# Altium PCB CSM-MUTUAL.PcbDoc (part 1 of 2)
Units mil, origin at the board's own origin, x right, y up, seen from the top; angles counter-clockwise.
Board outline 5500 x 4000 mil, 2 copper layers (Top Layer, Bottom Layer), stack 62 mil thick; 159 components, 115 nets, 998 pads, 195 vias.
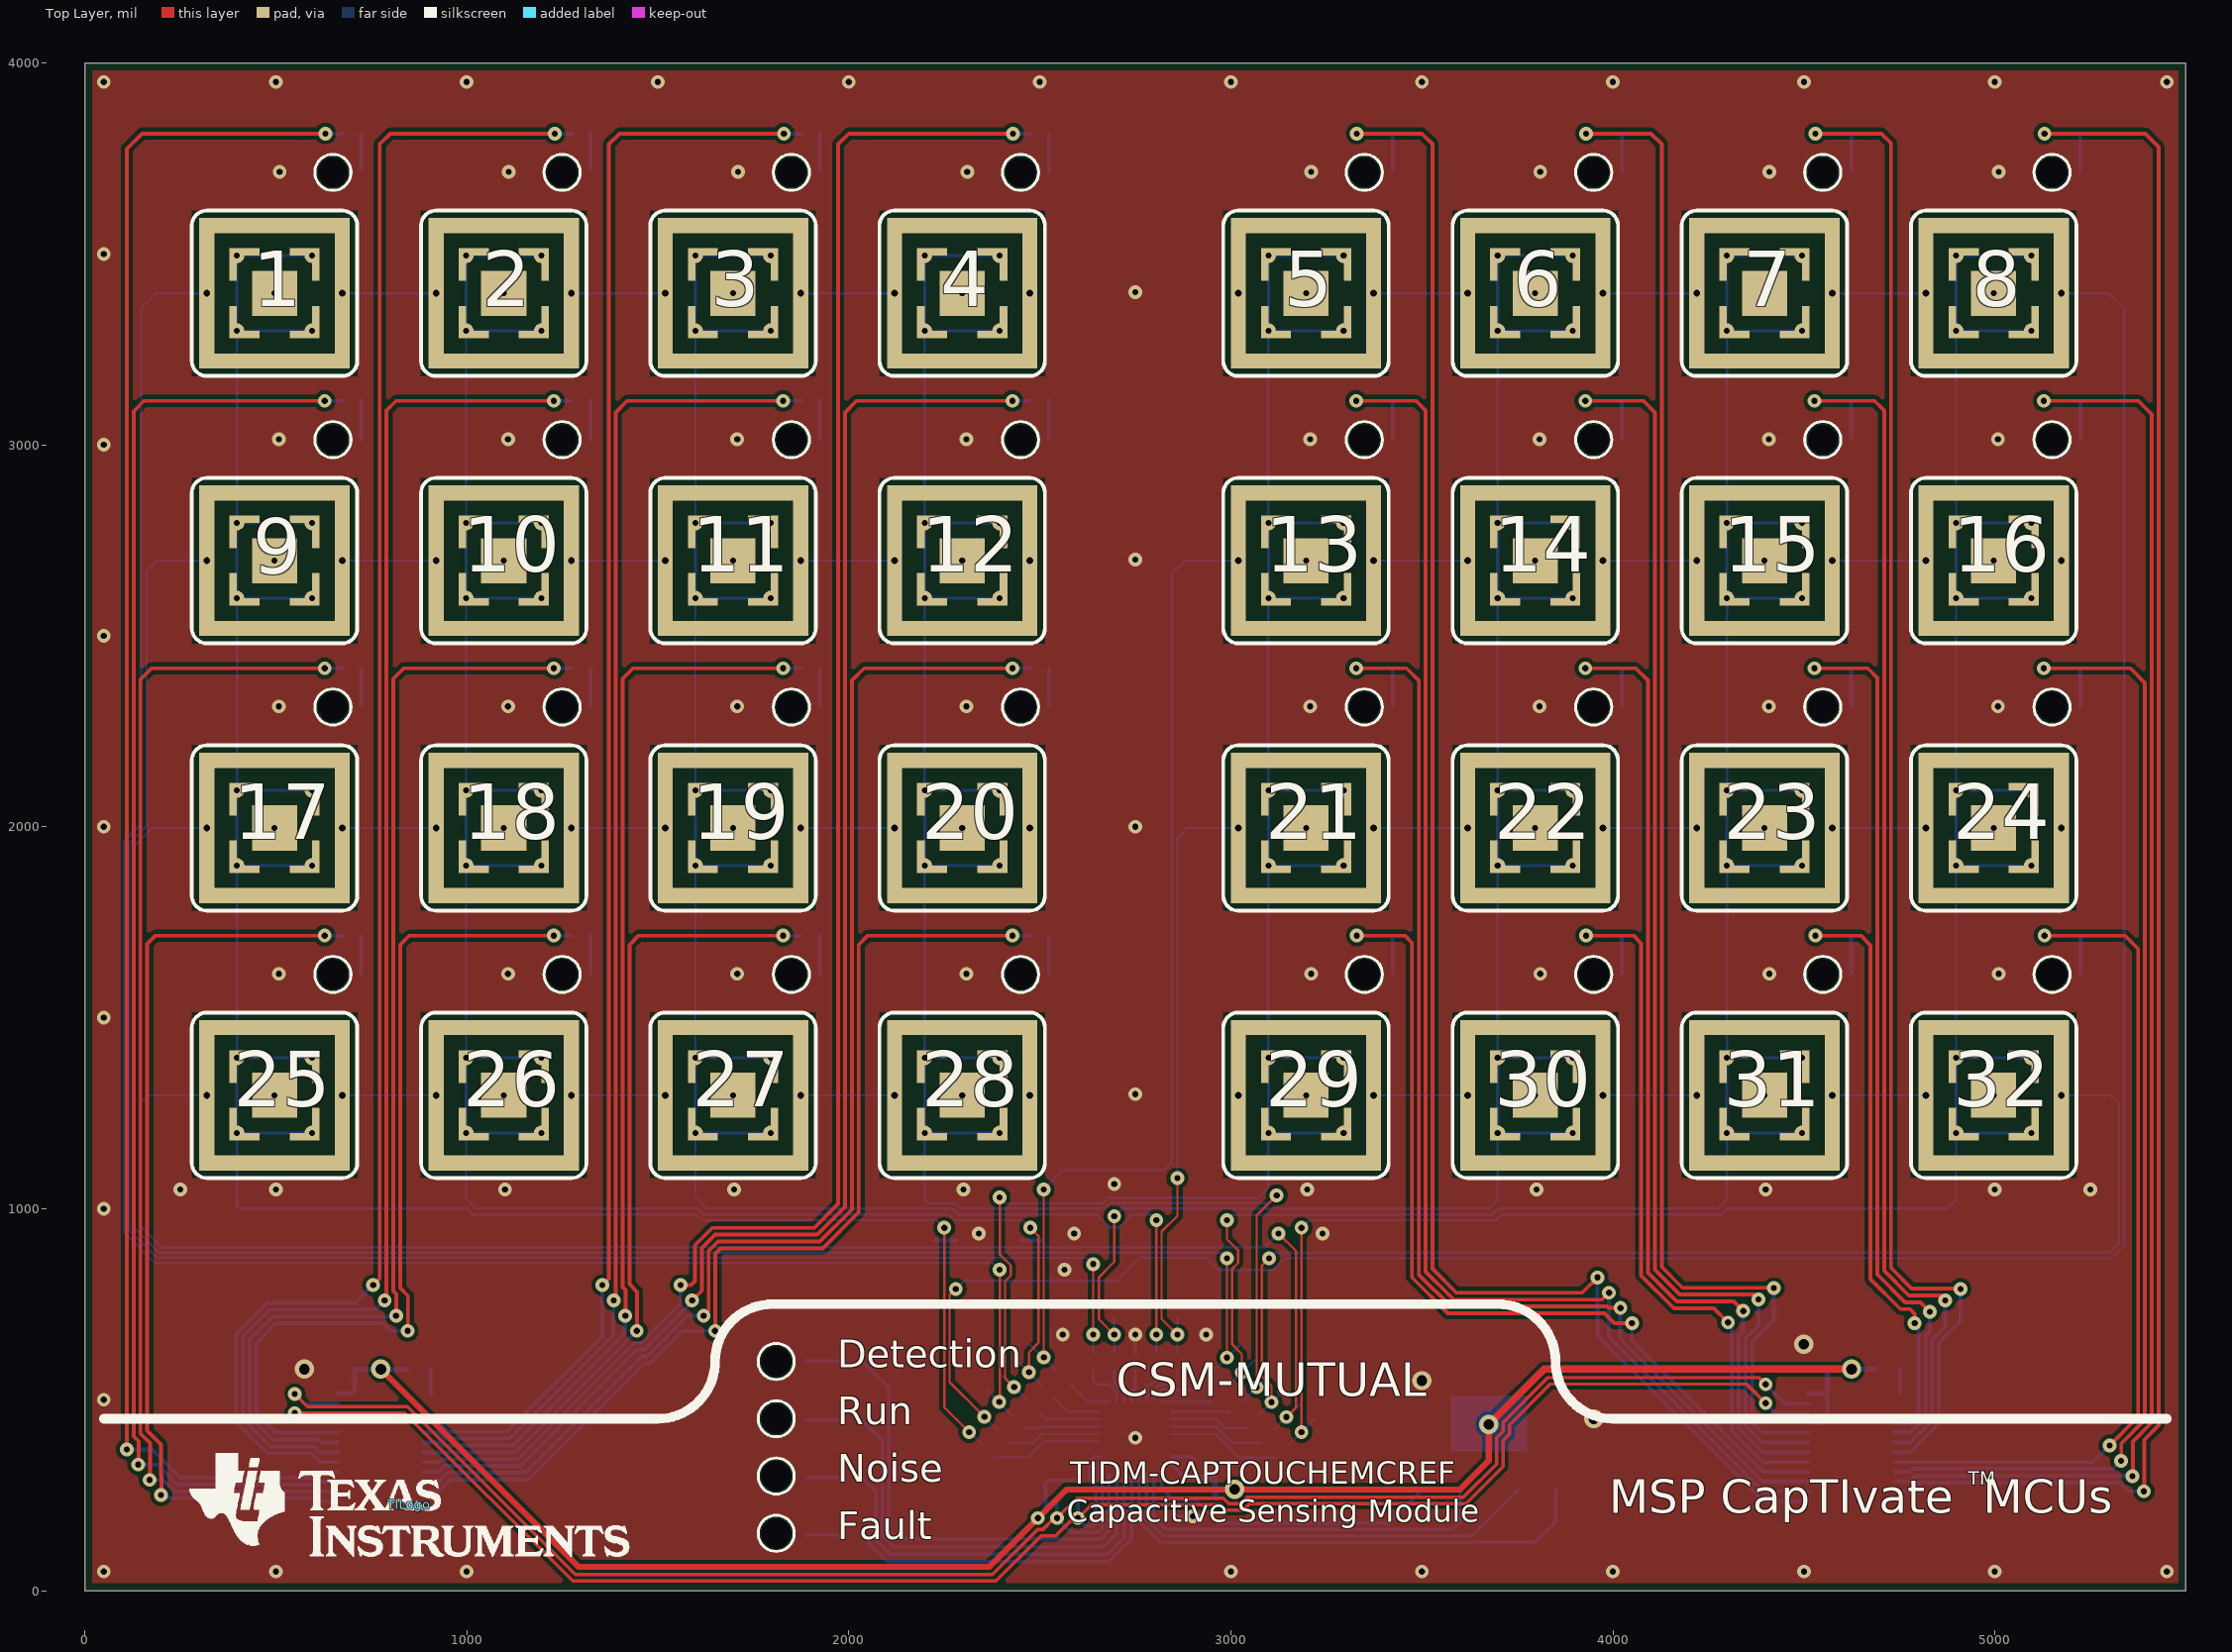
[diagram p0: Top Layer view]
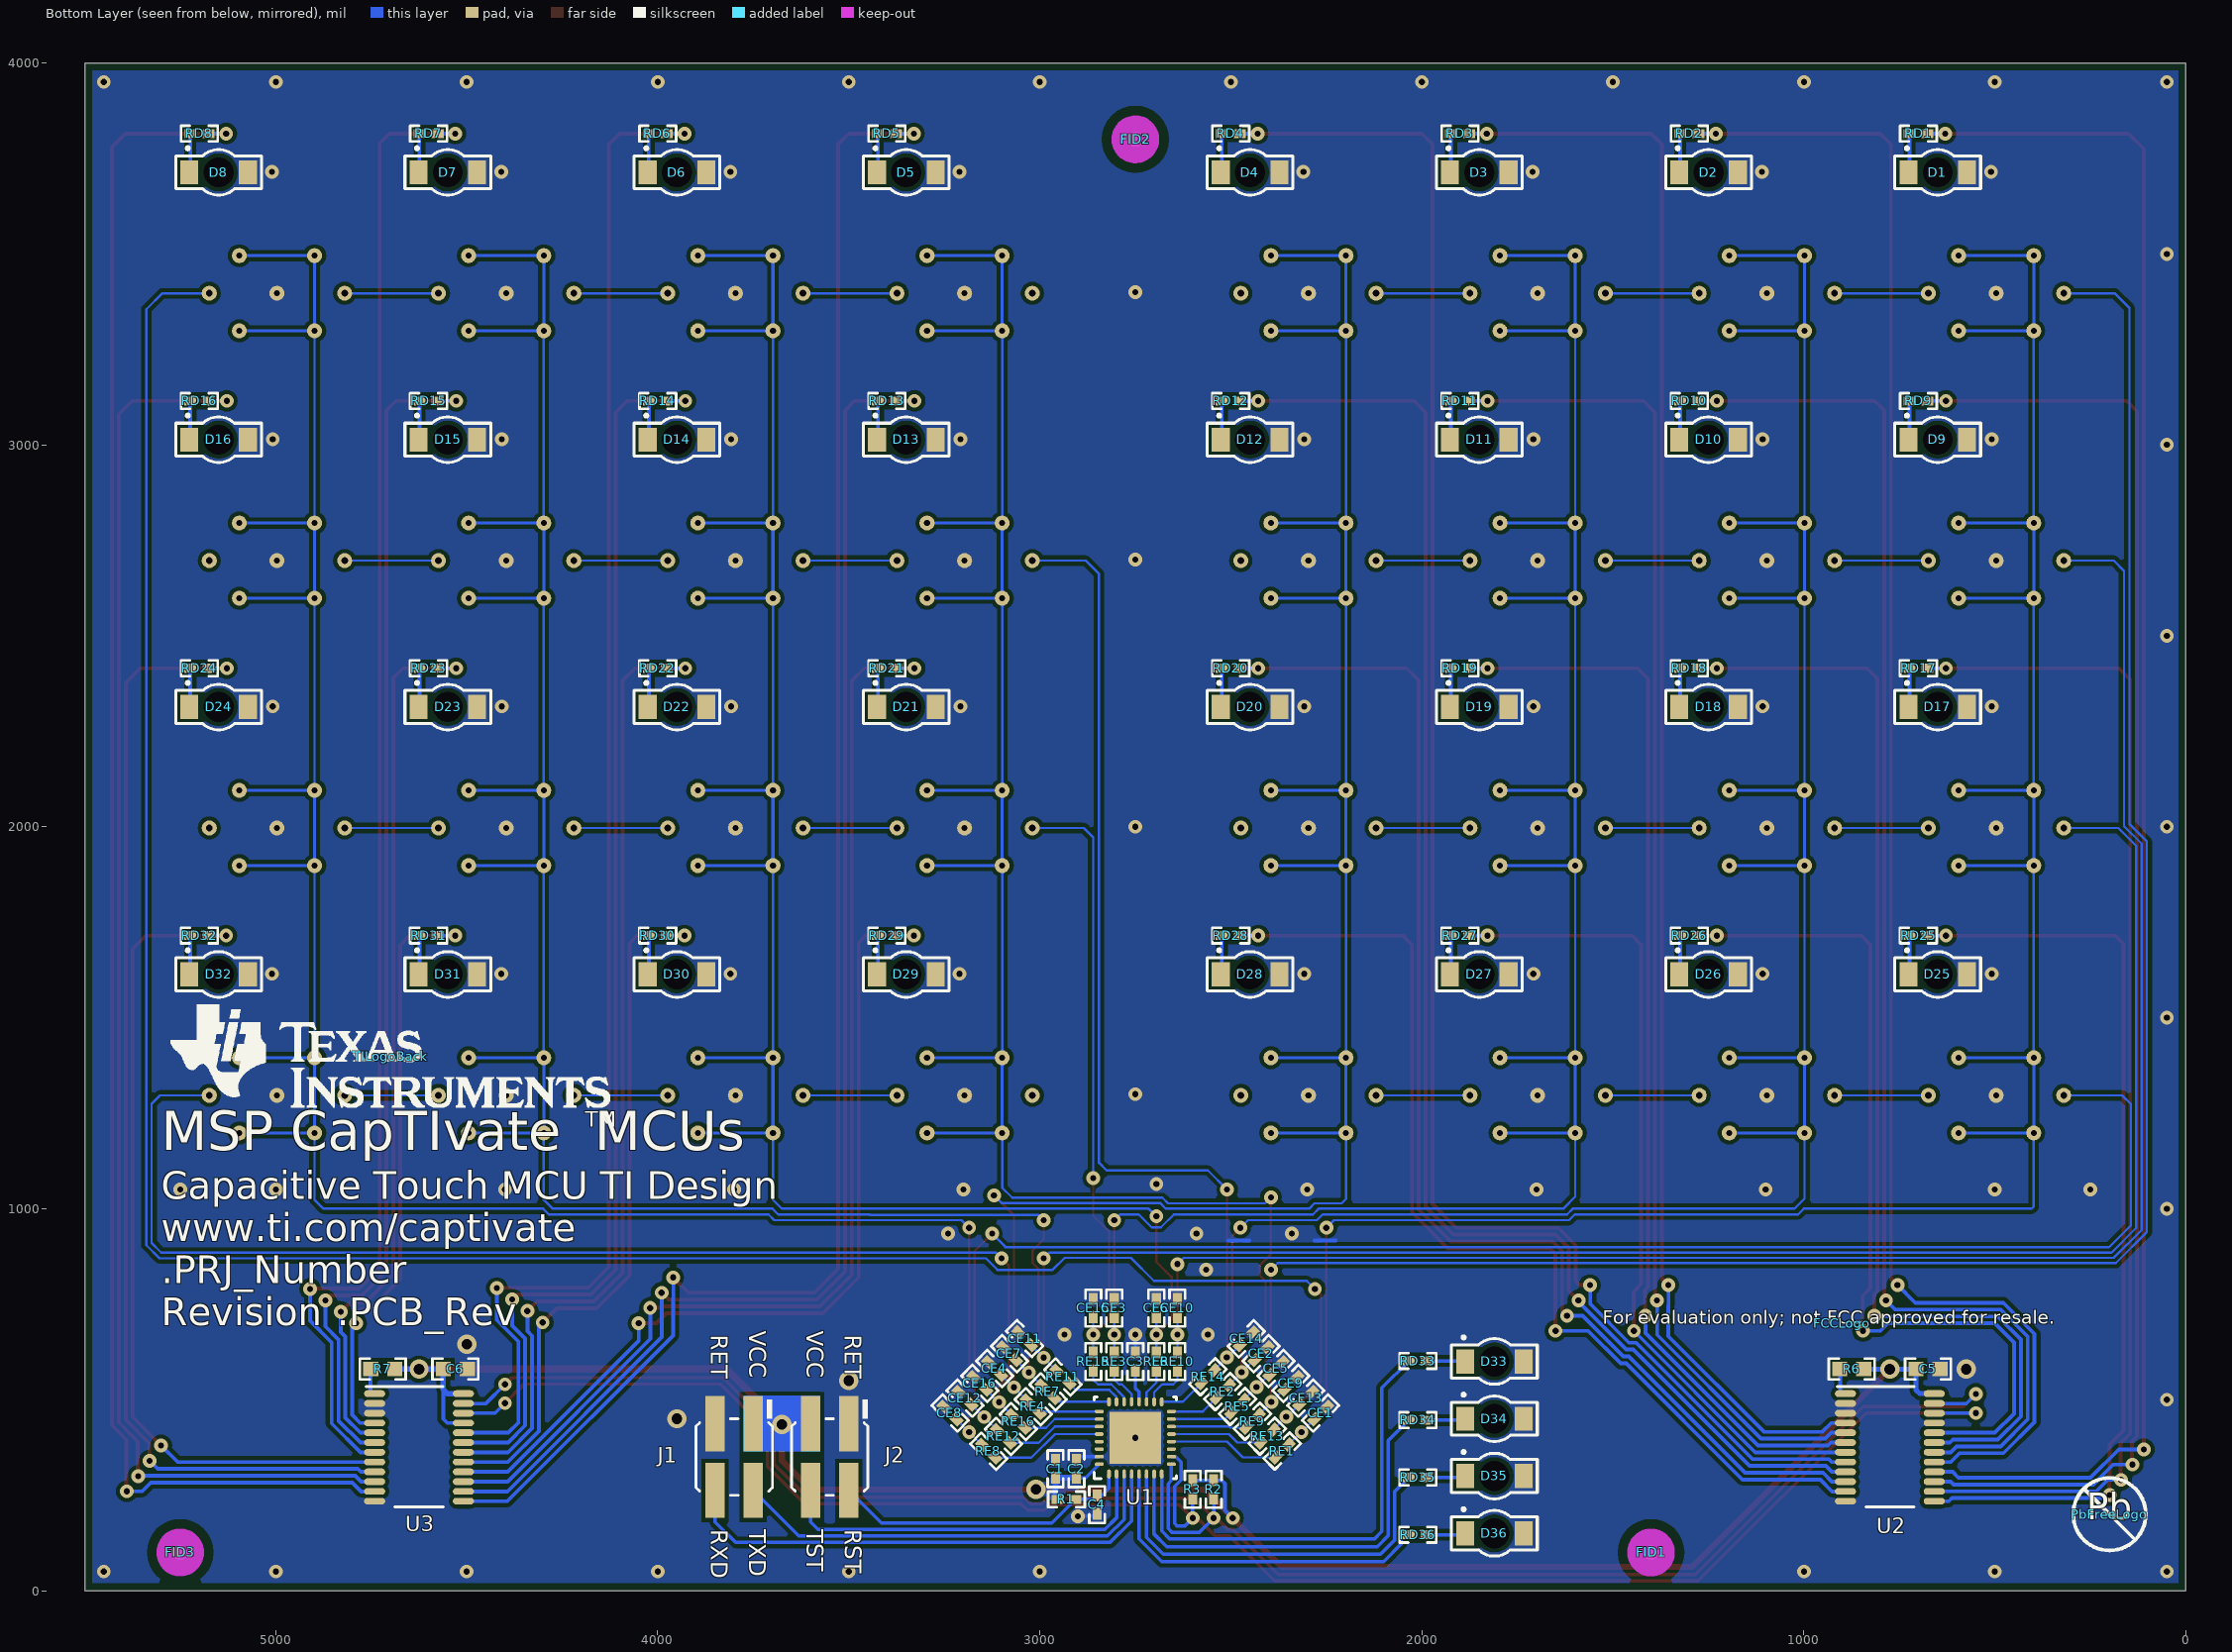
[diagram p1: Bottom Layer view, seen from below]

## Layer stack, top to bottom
Top Solder: solder mask 0.4, Solder Resist, Dk 3.5
Top Layer: signal copper 1.4
Dielectric1: core 59.2, FR-4, Dk 4.8
Bottom Layer: signal copper 1.4
Bottom Solder: solder mask 0.4, Solder Resist, Dk 3.5

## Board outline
0,0 0,4000 5500,4000 5500,0

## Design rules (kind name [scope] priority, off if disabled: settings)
AcuteAngle [All] p1: minimum=4.50000000000000E+0001 checktracksonly=FALSE
AssemblyTestPointUsage [All] p1: valid=2
Clearance Clearance_Keepouts [((IsTrack Or IsArc) And Not InPoly) And IsFree and IsKeepOut vs ((IsTrack Or IsArc) And Not InPoly) And IsFree and IsKeepOut] p1: gap=0
Clearance Clearance_BoardEdge_MountingHoles [OnCopper and InComponentClass('Mounting Holes') vs IsKeepOut] p2: gap=40
Clearance Clearance_BoardEdge_Poly [OnCopper and InPoly vs IsKeepOut] p3: gap=25
Clearance Clearance_BoardEdge [OnCopper and Not InComponentClass('Logo') and not InComponentClass('FiducialMark') and not InRegion(1000,500,4000,800) and Not IsKeepout vs IsKeepOut] p4: gap=75
Clearance Clearance_Poly [InPolygon] p5: gap=10
Clearance [All] p6: gap=7.87
ComponentClearance ComponentClearance_MountingHoles_FiducialMarks [InComponentClass('Mounting Holes') vs InComponentClass('FiducialMark')] p1: gap=50 collisioncheckmode=3 verticalgap=10 showdistances=FALSE
ComponentClearance ComponentClearance_Shunt [InComponentClass('Header') vs InComponentClass('Shunt')] p2: gap=0 collisioncheckmode=3 verticalgap=0 showdistances=FALSE
ComponentClearance ComponentClearance_Logo [InComponentClass('Logo')] p3: gap=50 collisioncheckmode=3 verticalgap=10 showdistances=FALSE
ComponentClearance ComponentClearance_ScrewToNut [(HasFootprint('NY PMS 440 0025 PH')) vs (HasFootprint('Keystone_1902C'))] p4: gap=5 collisioncheckmode=3 verticalgap=10 showdistances=FALSE
ComponentClearance ComponentClearance_MountingHoles [InComponentClass('Mounting Holes')] p5: gap=250 collisioncheckmode=3 verticalgap=100000 showdistances=FALSE
ComponentClearance ComponentClearance_SmallPassives [HasFootprint('0201*') or HasFootprint('0402*') or HasFootprint('0508') or HasFootprint('0603*') or HasFootprint('0612') or HasFootprint('0805*') or HasFootprint('0815*') or HasFootprint('0830*') or HasFootprint('1206*') or HasFootprint('1210*') or HasFootprint('1808*') or HasFootprint('1812*') or HasFootprint('1825*') or HasFootprint('2010*') or HasFootprint('2220*') or HasFootprint('2225*') or HasFootprint('2512*') or HasFootprint('2728*') or HasFootprint('3518*') vs HasFootprint('0201*') or HasFootprint('0402*') or HasFootprint('0508') or HasFootprint('0603*') or HasFootprint('0612') or HasFootprint('0805*') or HasFootprint('0815*') or HasFootprint('0830*') or HasFootprint('1206*') or HasFootprint('1210*') or HasFootprint('1808*') or HasFootprint('1812*') or HasFootprint('1825*') or HasFootprint('2010*') or HasFootprint('2220*') or HasFootprint('2225*') or HasFootprint('2512*') or HasFootprint('2728*') or HasFootprint('3518*')] p6: gap=15 collisioncheckmode=3 verticalgap=10 showdistances=FALSE
ComponentClearance ComponentClearance_THtoSMT [IsThruComponent vs IsSMTComponent] p7: gap=100 collisioncheckmode=3 verticalgap=30 showdistances=FALSE
ComponentClearance ComponentClearance_THtoTH [IsThruComponent vs IsThruComponent] p8: gap=25 collisioncheckmode=3 verticalgap=30 showdistances=FALSE
ComponentClearance [All] p9: gap=30 collisioncheckmode=3 verticalgap=10 showdistances=FALSE
DiffPairsRouting [All] p1: maxlimit=100 minlimit=10 mostfreqgap=10 toplayer_minwidth=15 toplayer_maxwidth=15 toplayer_prefwidth=15 bottomlayer_minwidth=15 bottomlayer_maxwidth=15 bottomlayer_prefwidth=15 maxuncoupledlength=1000
FabricationTestPointUsage TestPointUsage [All] p1: valid=2 allowmultiple=FALSE
FabricationTestpoint Testpoint [All] p1: side=3 testpointundercomponent=TRUE minsize=40 maxsize=100 preferedsize=60 minholesize=0 maxholesize=40 preferedholesize=32 testpointgrid=1 allowsidetop=TRUE allowsidebottom=TRUE usegrid=TRUE gridtolerance=0.01
FanoutControl Fanout_LCC [IsLCC] p1: bgadir=Out bgaviamode=Centered fanoutstyle=Auto fanoutdirection=Alternating viagrid=1 // Fanout_LCC (Default Rule)
FanoutControl Fanout_BGA [IsBGA] p2: bgadir=Out bgaviamode=Centered fanoutstyle=Auto fanoutdirection=Alternating viagrid=1 // Fanout_BGA (Default Rule)
FanoutControl Fanout_Default [All] p4: bgadir=Out bgaviamode=Centered fanoutstyle=Auto fanoutdirection=Alternating viagrid=1 // Fanout_Default (Default Rule)
FanoutControl Fanout_Small [(CompPinCount < 5)] p5: bgadir=Out bgaviamode=Centered fanoutstyle=Auto fanoutdirection=OutThenIn viagrid=1 // Fanout_Small (Default Rule)
HoleSize [All] p1: absolutevalues=TRUE maxlimit=251 minlimit=8 maxpercent=80.000 minpercent=20.000
MinimumAnnularRing MinimumAnnularRing_ThermalPadVias [IsVia and InAnyComponent] p1: minimumring=5.91
MinimumAnnularRing [All] p2: minimumring=9
MinimumSolderMaskSliver MinimumSolderMaskSliver_Logo [InComponentClass('Logo') vs InComponentClass('Logo')] p1: minsoldermaskwidth=0.7
MinimumSolderMaskSliver [All] p2: minsoldermaskwidth=3.94
PlaneConnect [All] p1: planeconnectstyle=Direct reliefexpansion=10 reliefentries=4 reliefconductorwidth=10 reliefairgap=10
PolygonConnect [All] p1: connectstyle=Direct reliefconductorwidth=10 reliefentries=4 polygonreliefangle="90 Angle" airgapwidth=10
RoutingVias ThermalPadVias [IsVia and InAnyComponent] p1: holewidth=7.87 width=19.68 viastyle="Through Hole" minholewidth=7.87 minwidth=19.68 maxholewidth=12.99 maxwidth=23.62
RoutingVias [All] p2: holewidth=16 width=34 viastyle="Through Hole" minholewidth=7.87 minwidth=26 maxholewidth=40 maxwidth=65
SilkToBoardRegionClearance [Not ((IsComment or IsDesignator) And (Hide <> 'False')) and not InRegion(1000,500,4000,800)] p1:
SilkToSilkClearance SilkToSilkClearance_Pb-FreeLogo [(HasFootprint('Pb-Free_Overlay_Medium') OR HasFootprint('Pb-Free_Overlay_Small')) vs (HasFootprint('Pb-Free_Overlay_Medium') OR HasFootprint('Pb-Free_Overlay_Small'))] p1: silktosilkclearance=0
SilkToSilkClearance [All] p2: silktosilkclearance=5
SilkToSolderMaskClearance "Silk to Solder Mask Opening" [All] p1: minsilkscreentomaskgap=1 clearancetoexposedcopper=FALSE
SolderMaskExpansion [All] p1: expansion=1.9
Width [All] p1: maxlimit=100 minlimit=6 preferedwidth=10 checkconnectedcopper=TRUE
15 further rules are at their usual default settings.

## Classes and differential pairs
component class Logo: TILogo TILogoBack
component class CSM-MUTUAL__TopLevel: FCCLogo FID1 FID2 FID3 PbFreeLogo TILogo TILogoBack
net class LED[1..32]: LED1 LED2 LED3 LED4 LED5 LED6 LED7 LED8 LED9 LED10 LED11 LED12 LED13 LED14 LED15 LED16 LED17 LED18 LED19 LED20 LED21 LED22 LED23 LED24 LED25 LED26 LED27 LED28 LED29 LED30 LED31 LED32
component class Header: J1 J2
component class CSM-MUTUAL__CapacitiveTouch: 1 2 3 4 5 6 7 8 9 10 11 12 13 14 15 16 17 18 19 20 21 22 23 24 25 26 27 28 29 30 31 32 CE1 CE2 CE3 CE4 CE5 CE6 CE7 CE8 CE9 CE10 CE11 CE12 CE13 CE14 CE15 CE16 RE1 RE2 RE3 RE4 RE5 RE6 RE7 RE8 RE9 RE10 RE11 RE12 RE13 RE14 RE15 RE16
component class CSM-MUTUAL__MCU: C1 C2 C3 C4 J1 J2 R1 R2 R3 U1
component class CSM-MUTUAL__LEDDrive: C5 C6 D1 D2 D3 D4 D5 D6 D7 D8 D9 D10 D11 D12 D13 D14 D15 D16 D17 D18 D19 D20 D21 D22 D23 D24 D25 D26 D27 D28 D29 D30 D31 D32 D33 D34 D35 D36 R6 R7 RD1 RD2 RD3 RD4 RD5 RD6 RD7 RD8 RD9 RD10 RD11 RD12 RD13 RD14 RD15 RD16 RD17 RD18 RD19 RD20 RD21 RD22 RD23 RD24 RD25 RD26 RD27 RD28 RD29 RD30 RD31 RD32 RD33 RD34 RD35 RD36 U2 U3
component class FiducialMark: FID1 FID2 FID3

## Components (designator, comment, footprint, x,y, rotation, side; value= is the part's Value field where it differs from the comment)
1 "Btn-Mutual-EMC" btn-mutual-emc-l-rotated 300,3200 r0 top
2 "Btn-Mutual-EMC" btn-mutual-emc-l-rotated 900,3200 r0 top
3 "Btn-Mutual-EMC" btn-mutual-emc-l-rotated 1500,3200 r0 top
4 "Btn-Mutual-EMC" btn-mutual-emc-l-rotated 2100,3200 r0 top
5 "Btn-Mutual-EMC" btn-mutual-emc-l-rotated 3000,3200 r0 top
6 "Btn-Mutual-EMC" btn-mutual-emc-l-rotated 3600,3200 r0 top
7 "Btn-Mutual-EMC" btn-mutual-emc-l-rotated 4200,3200 r0 top
8 "Btn-Mutual-EMC" btn-mutual-emc-l-rotated 4800,3200 r0 top
9 "Btn-Mutual-EMC" btn-mutual-emc-l-rotated 300,2500 r0 top
10 "Btn-Mutual-EMC" btn-mutual-emc-l-rotated 900,2500 r0 top
11 "Btn-Mutual-EMC" btn-mutual-emc-l-rotated 1500,2500 r0 top
12 "Btn-Mutual-EMC" btn-mutual-emc-l-rotated 2100,2500 r0 top
13 "Btn-Mutual-EMC" btn-mutual-emc-l-rotated 3000,2500 r0 top
14 "Btn-Mutual-EMC" btn-mutual-emc-l-rotated 3600,2500 r0 top
15 "Btn-Mutual-EMC" btn-mutual-emc-l-rotated 4200,2500 r0 top
16 "Btn-Mutual-EMC" btn-mutual-emc-l-rotated 4800,2500 r0 top
17 "Btn-Mutual-EMC" btn-mutual-emc-l-rotated 300,1800 r0 top
18 "Btn-Mutual-EMC" btn-mutual-emc-l-rotated 900,1800 r0 top
19 "Btn-Mutual-EMC" btn-mutual-emc-l-rotated 1500,1800 r0 top
20 "Btn-Mutual-EMC" btn-mutual-emc-l-rotated 2100,1800 r0 top
21 "Btn-Mutual-EMC" btn-mutual-emc-l-rotated 3000,1800 r0 top
22 "Btn-Mutual-EMC" btn-mutual-emc-l-rotated 3600,1800 r0 top
23 "Btn-Mutual-EMC" btn-mutual-emc-l-rotated 4200,1800 r0 top
24 "Btn-Mutual-EMC" btn-mutual-emc-l-rotated 4800,1800 r0 top
25 "Btn-Mutual-EMC" btn-mutual-emc-l-rotated 300,1100 r0 top
26 "Btn-Mutual-EMC" btn-mutual-emc-l-rotated 900,1100 r0 top
27 "Btn-Mutual-EMC" btn-mutual-emc-l-rotated 1500,1100 r0 top
28 "Btn-Mutual-EMC" btn-mutual-emc-l-rotated 2100,1100 r0 top
29 "Btn-Mutual-EMC" btn-mutual-emc-l-rotated 3000,1100 r0 top
30 "Btn-Mutual-EMC" btn-mutual-emc-l-rotated 3600,1100 r0 top
31 "Btn-Mutual-EMC" btn-mutual-emc-l-rotated 4200,1100 r0 top
32 "Btn-Mutual-EMC" btn-mutual-emc-l-rotated 4800,1100 r0 top
C1 "C1005X5R0J475M050BC" 0402 2958.94,318.94 r90 bottom
C2 "C1005X5R0J104K" 0402 2903.94,318.94 r90 bottom
C3 "C1005X5R0J105M" 0402 2750,600 r90 bottom
C4 "GRM1555C1E511JA01D" 0402 2850,225 r270 bottom
C5 "0603YC104JAT2A" 0603 675,580 r180 bottom
C6 "0603YC104JAT2A" 0603 4530,580 r180 bottom
CE1 "GRM1555C1H680JA01D" 0402 2265,465 r135 bottom
CE2 "GRM1555C1H680JA01D" 0402 2420.56,620.56 r135 bottom
CE3 "GRM1555C1H680JA01D" 0402 2805,740 r90 bottom
CE4 "GRM1555C1H680JA01D" 0402 3118.33,581.67 r45 bottom
CE5 "GRM1555C1H680JA01D" 0402 2381.67,581.67 r135 bottom
CE6 "GRM1555C1H680JA01D" 0402 2695,740 r90 bottom
CE7 "GRM1555C1H680JA01D" 0402 3079.44,620.56 r45 bottom
CE8 "GRM1555C1H680JA01D" 0402 3235,465 r45 bottom
CE9 "GRM1555C1H680JA01D" 0402 2342.78,542.78 r135 bottom
CE10 "GRM1555C1H680JA01D" 0402 2640,740 r90 bottom
CE11 "GRM1555C1H680JA01D" 0402 3040,660 r45 bottom
CE12 "GRM1555C1H680JA01D" 0402 3196.11,503.89 r45 bottom
CE13 "GRM1555C1H680JA01D" 0402 2303.89,503.89 r135 bottom
CE14 "GRM1555C1H680JA01D" 0402 2459.45,659.45 r135 bottom
CE15 "GRM1555C1H680JA01D" 0402 2860,740 r90 bottom
CE16 "GRM1555C1H680JA01D" 0402 3157.22,542.78 r45 bottom
D1 "Orange LED" 1206_ReverseMount_LED 750,3745 r180 top
D2 "Orange LED" 1206_ReverseMount_LED 1350,3745 r180 top
D3 "Orange LED" 1206_ReverseMount_LED 1950,3745 r180 top
D4 "Orange LED" 1206_ReverseMount_LED 2550,3745 r180 top
D5 "Orange LED" 1206_ReverseMount_LED 3450,3745 r180 top
D6 "Orange LED" 1206_ReverseMount_LED 4050,3745 r180 top
D7 "Orange LED" 1206_ReverseMount_LED 4650,3745 r180 top
D8 "Orange LED" 1206_ReverseMount_LED 5250,3745 r180 top
D9 "Orange LED" 1206_ReverseMount_LED 750,3045 r180 top
D10 "Orange LED" 1206_ReverseMount_LED 1350,3045 r180 top
D11 "Orange LED" 1206_ReverseMount_LED 1950,3045 r180 top
D12 "Orange LED" 1206_ReverseMount_LED 2550,3045 r180 top
D13 "Orange LED" 1206_ReverseMount_LED 3450,3045 r180 top
D14 "Orange LED" 1206_ReverseMount_LED 4050,3045 r180 top
D15 "Orange LED" 1206_ReverseMount_LED 4650,3045 r180 top
D16 "Orange LED" 1206_ReverseMount_LED 5250,3045 r180 top
D17 "Orange LED" 1206_ReverseMount_LED 750,2345 r180 top
D18 "Orange LED" 1206_ReverseMount_LED 1350,2345 r180 top
D19 "Orange LED" 1206_ReverseMount_LED 1950,2345 r180 top
D20 "Orange LED" 1206_ReverseMount_LED 2550,2345 r180 top
D21 "Orange LED" 1206_ReverseMount_LED 3450,2345 r180 top
D22 "Orange LED" 1206_ReverseMount_LED 4050,2345 r180 top
D23 "Orange LED" 1206_ReverseMount_LED 4650,2345 r180 top
D24 "Orange LED" 1206_ReverseMount_LED 5250,2345 r180 top
D25 "Orange LED" 1206_ReverseMount_LED 750,1645 r180 top
D26 "Orange LED" 1206_ReverseMount_LED 1350,1645 r180 top
D27 "Orange LED" 1206_ReverseMount_LED 1950,1645 r180 top
D28 "Orange LED" 1206_ReverseMount_LED 2550,1645 r180 top
D29 "Orange LED" 1206_ReverseMount_LED 3450,1645 r180 top
D30 "Orange LED" 1206_ReverseMount_LED 4050,1645 r180 top
D31 "Orange LED" 1206_ReverseMount_LED 4650,1645 r180 top
D32 "Orange LED" 1206_ReverseMount_LED 5250,1645 r180 top
D33 "Yellow-Green LED" 1206_ReverseMount_LED 1910.39,631.5 r180 top
D34 "Yellow-Green LED" 1206_ReverseMount_LED 1910.39,481.5 r180 top
D35 "Yellow LED" 1206_ReverseMount_LED 1910.39,331.5 r180 top
D36 "Red LED" 1206_ReverseMount_LED 1910.39,181.5 r180 top
FCCLogo "FCC disclaimer" FCC_disclaimer 900,700 r180 bottom
FID1 "Fiducial" Fiducial10-30 1400,100 r180 bottom
FID2 "Fiducial" Fiducial10-30 2750,3800 r180 bottom
FID3 "Fiducial" Fiducial10-30 5250,100 r180 bottom
J1 "15-91-2040" Molex_15-91-2040 3799.99,350 r0 bottom
J2 "15-91-2040" Molex_15-91-2040 3550,350 r0 bottom
PbFreeLogo "Pb-Free Symbol" Pb-Free_Overlay_Medium 200,200 r180 bottom
R1 "CRCW040247K0JNED" 0402 2930.31,238.94 r0 bottom
R2 "CRCW04022K20JNED" 0402 2545,265 r270 bottom
R3 "CRCW04022K20JNED" 0402 2600,265 r270 bottom
R6 "CRCW060310K0JNEA" 0603 875,580 r0 bottom
R7 "CRCW060310K0JNEA" 0603 4720,580 r0 bottom
RD1 "CRCW0402620RJNED" 0402 700,3815 r0 bottom
RD2 "CRCW0402620RJNED" 0402 1300,3815 r0 bottom
RD3 "CRCW0402620RJNED" 0402 1900,3815 r0 bottom
RD4 "CRCW0402620RJNED" 0402 2500,3815 r0 bottom
RD5 "CRCW0402620RJNED" 0402 3400,3815 r0 bottom
RD6 "CRCW0402620RJNED" 0402 4000,3815 r0 bottom
RD7 "CRCW0402620RJNED" 0402 4600,3815 r0 bottom
RD8 "CRCW0402620RJNED" 0402 5200,3815 r0 bottom
RD9 "CRCW0402620RJNED" 0402 700,3115 r0 bottom
RD10 "CRCW0402620RJNED" 0402 1300,3115 r0 bottom
RD11 "CRCW0402620RJNED" 0402 1900,3115 r0 bottom
RD12 "CRCW0402620RJNED" 0402 2500,3115 r0 bottom
RD13 "CRCW0402620RJNED" 0402 3400,3115 r0 bottom
RD14 "CRCW0402620RJNED" 0402 4000,3115 r0 bottom
RD15 "CRCW0402620RJNED" 0402 4600,3115 r0 bottom
RD16 "CRCW0402620RJNED" 0402 5200,3115 r0 bottom
RD17 "CRCW0402620RJNED" 0402 700,2415 r0 bottom
RD18 "CRCW0402620RJNED" 0402 1300,2415 r0 bottom
RD19 "CRCW0402620RJNED" 0402 1900,2415 r0 bottom
RD20 "CRCW0402620RJNED" 0402 2500,2415 r0 bottom
RD21 "CRCW0402620RJNED" 0402 3400,2415 r0 bottom
RD22 "CRCW0402620RJNED" 0402 4000,2415 r0 bottom
RD23 "CRCW0402620RJNED" 0402 4600,2415 r0 bottom
RD24 "CRCW0402620RJNED" 0402 5200,2415 r0 bottom
RD25 "CRCW0402620RJNED" 0402 700,1715 r0 bottom
RD26 "CRCW0402620RJNED" 0402 1300,1715 r0 bottom
RD27 "CRCW0402620RJNED" 0402 1900,1715 r0 bottom
RD28 "CRCW0402620RJNED" 0402 2500,1715 r0 bottom
RD29 "CRCW0402620RJNED" 0402 3400,1715 r0 bottom
RD30 "CRCW0402620RJNED" 0402 4000,1715 r0 bottom
RD31 "CRCW0402620RJNED" 0402 4600,1715 r0 bottom
RD32 "CRCW0402620RJNED" 0402 5200,1715 r0 bottom
RD33 "CRCW0402620RJNED" 0402 2010.39,601.5 r180 bottom
RD34 "CRCW0402620RJNED" 0402 2010.39,446.5 r180 bottom
RD35 "CRCW0402620RJNED" 0402 2010.39,296.5 r180 bottom
RD36 "CRCW0402620RJNED" 0402 2010.39,146.5 r180 bottom
RE1 "CRCW0402470RJNED" 0402 2365.55,365.55 r315 bottom
RE2 "CRCW0402470RJNED" 0402 2521.11,521.11 r315 bottom
RE3 "CRCW0402470RJNED" 0402 2805,600 r270 bottom
RE4 "CRCW0402470RJNED" 0402 3017.23,481.66 r225 bottom
RE5 "CRCW0402470RJNED" 0402 2482.22,482.22 r315 bottom
RE6 "CRCW0402470RJNED" 0402 2695,600 r270 bottom
RE7 "CRCW0402470RJNED" 0402 2978.34,520.55 r225 bottom
RE8 "CRCW0402470RJNED" 0402 3133.9,364.99 r225 bottom
RE9 "CRCW0402470RJNED" 0402 2443.33,443.33 r315 bottom
RE10 "CRCW0402470RJNED" 0402 2640,600 r270 bottom
RE11 "CRCW0402470RJNED" 0402 2939.45,559.45 r225 bottom
RE12 "CRCW0402470RJNED" 0402 3095.01,403.88 r225 bottom
RE13 "CRCW0402470RJNED" 0402 2404.44,404.44 r315 bottom
RE14 "CRCW0402470RJNED" 0402 2560,560 r315 bottom
RE15 "CRCW0402470RJNED" 0402 2860,600 r270 bottom
RE16 "CRCW0402470RJNED" 0402 3056.12,442.77 r225 bottom
TILogo "Texas Instruments" TI_Stacked_Overlay_Medium 850,225 r0 top
TILogoBack "Texas Instruments" TI_Stacked_Overlay_Medium 4700,1400 r180 bottom
U1 "MSP430FR2633IRHB" RHB0032E_NV 2750,400 r90 bottom
U2 "TCA9535PWR" PW0024A_N 775,375 r180 bottom
U3 "TCA9535PWR" PW0024A_N 4625,375 r180 bottom

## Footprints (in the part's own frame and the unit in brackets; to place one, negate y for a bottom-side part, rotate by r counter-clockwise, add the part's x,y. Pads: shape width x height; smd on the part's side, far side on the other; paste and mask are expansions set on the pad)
0402 [mm] "0402 from SM-752 data"
  rect 0.8x0.6 smd: 1(-0.6,0) 2(0.6,0)
  silkscreen extent -1.22,-0.52 1.22,0.52, body extent -0.55,-0.3 0.55,0.3, height 0.6
0603 [mm] "0603 from SM-752 data"
  rect 1x0.95 smd: 1(-0.8,0) 2(0.8,0)
  silkscreen extent -1.52,-0.69 1.52,0.69, body extent -0.87,-0.47 0.87,0.47, height 1
1206_ReverseMount_LED [mm]
  rect 1.2x1.6 smd far side: 1(0.6,0.8) 2(4.5,0.8)
  round 0 hole 2 unplated: ""(2.55,0.8)
  silkscreen extent 1.35,-0.4 3.75,2
btn-mutual-emc-l-rotated [mm] "EMC Mutual Capacitance Button for Large Overlays (>1.5mm)"
  rect 3x3 smd paste+0: GND(5,5)
  round 1 hole 0.4: GND(5,5) RX(2.5,2.5) RX(2.5,7.5) RX(7.5,2.5) RX(7.5,7.5)
  rect 0.5x1.667 smd paste+0: RX(2.25,3.333) RX(2.25,6.667) RX(7.75,3.333) RX(7.75,6.667)
  rect 2x0.5 smd paste+0: RX(3,2.25) RX(3,7.75) RX(7,2.25) RX(7,7.75)
  rect 1x10 smd paste+0: TX(0.5,5) TX(9.5,5)
  round 1 hole 0.45: TX(0.5,5) TX(9.5,5)
  rect 10x1 smd paste+0: TX(5,0.5) TX(5,9.5)
  Top Layer pour cut-out: -0.5,10.5 10.5,10.5 10.5,-0.5 -0.5,-0.5
  Bottom Layer lines w0.2: 7.5,2.5 2.5,2.5 2.5,7.5 7.5,7.5
  silkscreen extent -0.5,-0.5 10.5,10.5
FCC_disclaimer [mil]
Fiducial10-30 [mm]
  round 1 smd mask+1: 1(0,0)
  Top Layer keep-out circle w1.678: c0,0 r0.75
Molex_15-91-2040 [mil] "Molex"
  rect 50x144.88 smd: 1(-50,-87.5) 2(-50,87.5) 3(50,-87.5) 4(50,87.5)
  silkscreen extent -100,-150 100,100, body extent -100,-137 100,138, height 380
Pb-Free_Overlay_Medium [mil]
  silkscreen extent -95,-95 95,95
PW0024A_N [mm] "TSOP, 24-Leads, Body 7.8x4.4mm, Pitch 0.65mm, IPC Medium Density"
  oval 1.4x0.45 smd: 1(-2.95,3.575) 2(-2.95,2.925) 3(-2.95,2.275) 4(-2.95,1.625) 5(-2.95,0.975) 6(-2.95,0.325) 7(-2.95,-0.325) 8(-2.95,-0.975) 9(-2.95,-1.625) 10(-2.95,-2.275) 11(-2.95,-2.925) 12(-2.95,-3.575) 13(2.95,-3.575) 14(2.95,-2.925) 15(2.95,-2.275) 16(2.95,-1.625) 17(2.95,-0.975) 18(2.95,-0.325) 19(2.95,0.325) 20(2.95,0.975) 21(2.95,1.625) 22(2.95,2.275) 23(2.95,2.925) 24(2.95,3.575)
  silkscreen extent -3.51,-3.95 1.6,4.04, body extent -3.21,-3.9 3.21,3.9, height 1
RHB0032E_NV [mm] "QFN, 32-Leads, Body 5x5mm, Pitch 0.5mm, Thermal Pad 3.45x3.45mm, TI Recommended"
  oval 0.6x0.24 smd: 1(-2.4,1.75) 2(-2.4,1.25) 3(-2.4,0.75) 4(-2.4,0.25) 5(-2.4,-0.25) 6(-2.4,-0.75) 7(-2.4,-1.25) 8(-2.4,-1.75) 17(2.4,-1.75) 18(2.4,-1.25) 19(2.4,-0.75) 20(2.4,-0.25) 21(2.4,0.25) 22(2.4,0.75) 23(2.4,1.25) 24(2.4,1.75)
  oval 0.24x0.6 smd: 9(-1.75,-2.4) 10(-1.25,-2.4) 11(-0.75,-2.4) 12(-0.25,-2.4) 13(0.25,-2.4) 14(0.75,-2.4) 15(1.25,-2.4) 16(1.75,-2.4) 25(1.75,2.4) 26(1.25,2.4) 27(0.75,2.4) 28(0.25,2.4) 29(-0.25,2.4) 30(-0.75,2.4) 31(-1.25,2.4) 32(-1.75,2.4)
  rect 3.45x3.45 smd paste-1.725: 33(0,0)
  silkscreen extent -2.72,-2.73 2.72,2.73, body extent -2.57,-2.57 2.58,2.58, height 1.01
TI_Stacked_Overlay_Medium [mil]
  silkscreen extent -576,-136 576,134

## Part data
1 2 3 4 5 6 7 8 9 10 11 12 13 14 15 16 17 18 19 20 21 22 23 24 25 26 27 28 29 30 31 32: library part btn-mutual-emc, "Capacitive Button, Mutual, 2-layer, EMC"
C1: "CAP, CERM, 4.7 µF, 6.3 V, +/- 20%, X5R, 0402"
C2: "CAP, CERM, 0.1 µF, 6.3 V, +/- 10%, X5R, 0402"
C3: "CAP, CERM, 1 µF, 6.3 V, +/- 20%, X5R, 0402"
C4: "CAP, CERM, 510 pF, 25 V, +/- 5%, C0G/NP0, 0402"
C5 C6: "CAP, CERM, 0.1 µF, 16 V, +/- 5%, X7R, 0603"
CE1 CE2 CE3 CE4 CE5 CE6 CE7 CE8 CE9 CE10 CE11 CE12 CE13 CE14 CE15 CE16: "CAP, CERM, 68 pF, 50 V, +/- 5%, C0G/NP0, 0402"
D1 D2 D3 D4 D5 D6 D7 D8 D9 D10 D11 D12 D13 D14 D15 D16 D17 D18 D19 D20 D21 D22 D23 D24 D25 D26 D27 D28 D29 D30 D31 D32: library part 597-6201-607F, "LED, Orange, SMD, Reverse Mount, 1206"
D33 D34: library part 597-6501-607F, "LED, Yellow-Green, SMD, Reverse Mount, 1206"
D35: library part 597-6401-607F, "LED, Yellow, SMD, Reverse Mount, 1206"
D36: library part 597-6001-607F, "LED, Red, SMD, Reverse Mount, 1206"
FCCLogo: library part FCC_disclaimer, "FCC_disclaimer"
FID1 FID2 FID3: "Fiducial mark.  There is nothing to buy or mount."
J1 J2: "Header, 100mil, 2x2, Tin, SMT"
PbFreeLogo: library part Pb-Free
R1: "RES, 47 k, 5%, 0.063 W, 0402"
R2 R3: "RES, 2.2 k, 5%, 0.063 W, 0402"
R6 R7: "RES, 10 k, 5%, 0.1 W, 0603"
RD1 RD2 RD3 RD4 RD5 RD6 RD7 RD8 RD9 RD10 RD11 RD12 RD13 RD14 RD15 RD16 RD17 RD18 RD19 RD20 RD21 RD22 RD23 RD24 RD25 RD26 RD27 RD28 RD29 RD30 RD31 RD32 RD33 RD34 RD35 RD36: "RES, 620, 5%, 0.063 W, 0402"
RE1 RE2 RE3 RE4 RE5 RE6 RE7 RE8 RE9 RE10 RE11 RE12 RE13 RE14 RE15 RE16: "RES, 470, 5%, 0.063 W, 0402"
TILogo TILogoBack: library part TI_Logo, "Texas Instrument Corporate Signature"
U1: "MSP430 Captivate Microcontroller"
U2 U3: "Remote 16-Bit I2C and SMBus, Low-Power I/O Expander with Interrupt Output and Config Register, 1.65 to 5.5 V, -40 to 85 degC, 24-pin TSSOP (PW), Green (RoHS & no Sb/Br)"

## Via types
v1: diameter 36, hole 16, Top Layer to Bottom Layer, tented both sides, 186 vias
v2: diameter 50, hole 28, Top Layer to Bottom Layer, tented both sides, 8 vias
v3: diameter 36, hole 16, Top Layer to Bottom Layer, 1 vias

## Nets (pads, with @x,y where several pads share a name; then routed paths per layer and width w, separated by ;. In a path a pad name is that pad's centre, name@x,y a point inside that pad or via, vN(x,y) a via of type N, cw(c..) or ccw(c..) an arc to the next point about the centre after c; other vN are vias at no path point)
BANKA_RX0: 1.RX 9.RX 17.RX 25.RX CE1.1 RE1.1 | length 4234.6
  Top Layer w6: v1(2250,950) 2250,480 v1(2315,415)
  Bottom Layer w6: 25.RX@398.43,1198.43 398.43,1005.2 403.62,1000 1000,1000 1015,985 1600,985 1615,970 2230,970 v1(2250,950) ; 25.RX@398.43,1395.28 17.RX@398.43,1898.43 ; 17.RX@398.43,2095.28 9.RX@398.43,2598.43 ; 9.RX@398.43,2795.28 1.RX@398.43,3298.43 ; CE1.1@2282.79,448.3 CE1.1@2281.7,448.3 v1(2315,415) 2316.09,415 RE1.1@2348.84,382.25
BANKA_RX1: 2.RX 10.RX 18.RX 26.RX CE2.1 RE2.1 | length 3682
  Top Layer w6: v1(2471.67,571.67) 2471.67,623.69 2496.13,648.14 2496.13,928.87 v1(2475,950)
  Bottom Layer w6: 26.RX@998.43,1198.43 998.43,1026.57 1025,1000 1605,1000 1620,985 2260,985 2275,970 2455,970 v1(2475,950) ; 26.RX@998.43,1395.28 18.RX@998.43,1898.43 ; 18.RX@998.43,2095.28 10.RX@998.43,2598.43 ; 10.RX@998.43,2795.28 2.RX@998.43,3298.43 ; CE2.1@2437.27,603.86 2439.48,603.86 v1(2471.67,571.67) 2471.67,570.55 RE2.1@2504.41,537.81
BANKA_RX2: 3.RX 11.RX 19.RX 27.RX CE3.1 RE3.1 | length 3332.6
  Top Layer w6: v1(2805,670) v1(2805,970)
  Bottom Layer w6: 27.RX@1598.43,1198.43 1598.43,1031.57 1630,1000 2270,1000 2285,985 2649.17,985 2683.04,951.13 2706.96,951.13 2740.83,985 2790,985 v1(2805,970) ; 27.RX@1598.43,1395.28 19.RX@1598.43,1898.43 ; 19.RX@1598.43,2095.28 11.RX@1598.43,2598.43 ; 11.RX@1598.43,2795.28 3.RX@1598.43,3298.43 ; RE3.1@2805,623.62 v1(2805,670) ; v1@2805,673.44 v1(2805,670) ; CE3.1@2805,716.38 v1(2805,670)
BANKA_RX3: 4.RX 12.RX 20.RX 28.RX CE4.1 RE4.1 | length 3248.7
  Top Layer w6: v1(3067.78,532.22) 3067.78,982.78 v1(3120,1035)
  Bottom Layer w6: 28.RX@2198.43,1198.43 2198.43,1025.45 2210,1013.87 2281.13,1013.87 2295,1000 2670,1000 2685,1015 3100,1015 v1(3120,1035) ; 28.RX@2198.43,1395.28 20.RX@2198.43,1898.43 ; 20.RX@2198.43,2095.28 12.RX@2198.43,2598.43 ; 12.RX@2198.43,2795.28 4.RX@2198.43,3298.43 ; RE4.1@3033.93,498.37 v1(3067.78,532.22) 3068.87,532.22 CE4.1@3101.62,564.97
BANKA_TX0: 1.TX 2.TX 3.TX 4.TX CE9.1 RE9.1 | length 6138
  Top Layer w6: v1(2393.89,493.89) v1@2393.89,495 ; v1@2395,495 v1(2395,840)
  Bottom Layer w6: 1.TX@319.68,3396.85 186.85,3396.85 147.98,3357.98 147.98,2007.22 102.25,1961.49 102.25,938.51 183.25,857.5 2377.5,857.5 v1(2395,840) ; 1.TX@674.02,3396.85 2.TX@919.68,3396.85 ; 2.TX@1274.02,3396.85 3.TX@1519.68,3396.85 ; 3.TX@1874.02,3396.85 4.TX@2119.68,3396.85 ; CE9.1@2359.48,526.08 2361.7,526.08 v1(2393.89,493.89) 2393.89,492.76 RE9.1@2426.62,460.03
BANKA_TX1: 9.TX 10.TX 11.TX 12.TX CE10.1 RE10.1 | length 5489.3
  Top Layer w6: v1(2640,670) v1(2640,855)
  Bottom Layer w6: 9.TX@319.68,2696.85 188.7,2696.85 161.85,2670 161.85,2001.47 116.13,1955.75 116.13,944.25 189,871.38 2623.62,871.38 v1(2640,855) ; 9.TX@674.02,2696.85 10.TX@919.68,2696.85 ; 10.TX@1274.02,2696.85 11.TX@1519.68,2696.85 ; 11.TX@1874.02,2696.85 12.TX@2119.68,2696.85 ; RE10.1@2640,623.62 v1(2640,670) CE10.1@2640,716.38
BANKA_TX2: 17.TX 18.TX 19.TX 20.TX CE11.1 RE11.1 | length 5194.2
  Top Layer w6: v1(2990,610) v1(2990,870)
  Bottom Layer w6: 17.TX@319.68,1996.85 176.85,1996.85 130,1950 130,950 194.75,885.25 2974.75,885.25 v1(2990,870) ; 17.TX@674.02,1996.85 18.TX@919.68,1996.85 ; 18.TX@1274.02,1996.85 19.TX@1519.68,1996.85 ; 19.TX@1874.02,1996.85 20.TX@2119.68,1996.85 ; RE11.1@2956.15,576.15 v1(2990,610) CE11.1@3023.3,643.3
BANKA_TX3: 25.TX 26.TX 27.TX 28.TX CE12.1 RE12.1 | length 4865.7
  Top Layer w6: v1(3125,935) 3171.13,888.87 3171.13,480 v1(3145.56,454.44)
  Bottom Layer w6: 25.TX@319.68,1296.85 166.85,1296.85 143.87,1273.87 143.87,956.13 200.87,899.13 3090,899.13 3090,900 v1(3125,935) ; 25.TX@674.02,1296.85 26.TX@919.68,1296.85 ; 26.TX@1274.02,1296.85 27.TX@1519.68,1296.85 ; 27.TX@1874.02,1296.85 28.TX@2119.68,1296.85 ; RE12.1@3111.71,420.58 v1(3145.56,454.44) 3146.65,454.44 CE12.1@3179.41,487.19
BANKB_RX0: 5.RX 13.RX 21.RX 29.RX CE5.1 RE5.1 | length 3000.5
  Top Layer w6: v1(2395,1030) 2395,880.83 2423.87,851.96 2423.87,825 2408.87,810 2408.87,556.69 v1(2432.78,532.78)
  Bottom Layer w6: v1(2395,1030) 2411.13,1013.87 2664.25,1013.87 2679.25,1028.87 3072.3,1028.87 3098.43,1055 29.RX@3098.43,1198.43 ; CE5.1@2398.38,564.97 2400.59,564.97 v1(2432.78,532.78) 2465.51,500.05 RE5.1@2465.51,498.92 ; 29.RX@3098.43,1395.28 21.RX@3098.43,1898.43 ; 21.RX@3098.43,2095.28 13.RX@3098.43,2598.43 ; 13.RX@3098.43,2795.28 5.RX@3098.43,3298.43
BANKB_RX1: 6.RX 14.RX 22.RX 30.RX CE6.1 RE6.1 | length 3141.8
  Top Layer w6: v1(2695,670) 2655,710 2655,821.13 2695,861.13 v1(2695,980)
  Bottom Layer w6: RE6.1@2695,623.62 v1(2695,670) CE6.1@2695,716.38 ; v1(2695,980) 2715,1000 3675,1000 3698.43,1023.43 30.RX@3698.43,1198.43 ; 30.RX@3698.43,1395.28 22.RX@3698.43,1898.43 ; 22.RX@3698.43,2095.28 14.RX@3698.43,2598.43 ; 14.RX@3698.43,2795.28 6.RX@3698.43,3298.43
BANKB_RX2: 7.RX 15.RX 23.RX 31.RX CE7.1 RE7.1 | length 3537.7
  Top Layer w6: v1(2990,970) 2990,920 3018.87,891.13 3018.87,858.04 3003.87,843.04 3003.87,644.38 3028.89,619.36 v1(3028.89,571.11)
  Bottom Layer w6: v1(2990,970) 3003.87,983.87 3444.25,983.87 3445.38,985 3685,985 3700,1000 4275,1000 4298.43,1023.43 31.RX@4298.43,1198.43 ; RE7.1@2995.04,537.26 v1(3028.89,571.11) 3029.98,571.11 CE7.1@3062.73,603.86 ; 31.RX@4298.43,1395.28 23.RX@4298.43,1898.43 ; 23.RX@4298.43,2095.28 15.RX@4298.43,2598.43 ; 15.RX@4298.43,2795.28 7.RX@4298.43,3298.43
BANKB_RX3: 8.RX 16.RX 24.RX 32.RX CE8.1 RE8.1 | length 4058.6
  Top Layer w6: v1(3185,415) v1(3185,950)
  Bottom Layer w6: RE8.1@3150.6,381.69 3151.69,381.69 v1(3185,415) CE8.1@3218.3,448.3 ; v1(3185,950) 3205,970 3695,970 3710,985 4285,985 4300,1000 4875,1000 4898.43,1023.43 32.RX@4898.43,1198.43 ; 32.RX@4898.43,1395.28 24.RX@4898.43,1898.43 ; 24.RX@4898.43,2095.28 16.RX@4898.43,2598.43 ; 16.RX@4898.43,2795.28 8.RX@4898.43,3298.43
BANKB_TX0: 5.TX 6.TX 7.TX 8.TX CE13.1 RE13.1 | length 6975.5
  Top Layer w6: v1(2280,790) 2263.87,773.87 2263.87,546.13 v1(2355,455)
  Bottom Layer w6: v1(2280,790) 2301.13,811.13 2701.13,811.13 2761.38,871.38 2935,871.38 2966.38,840 3110.83,840 3140.83,870 5304.62,870 5338.87,904.25 5338.87,3354.83 5296.85,3396.85 8.TX@5174.02,3396.85 ; CE13.1@2320.59,487.19 2352.78,455 v1(2355,455) RE13.1@2387.73,422.27 ; 5.TX@3374.02,3396.85 6.TX@3619.69,3396.85 ; 6.TX@3974.02,3396.85 7.TX@4219.69,3396.85 ; 7.TX@4574.02,3396.85 8.TX@4819.69,3396.85
BANKB_TX1: 13.TX 14.TX 15.TX 16.TX CE14.1 RE14.1 | length 3366.9
  Top Layer w6: v1(2510,1050) 2510,611.13 v1(2510.56,610.56)
  Bottom Layer w6: CE14.1@2476.16,642.75 2508.34,610.56 v1(2510.56,610.56) 2510.56,609.44 RE14.1@2543.3,576.7 ; v1(2510,1050) 2560,1100 2825,1100 2845,1120 2845,2661.85 2880,2696.85 13.TX@3019.68,2696.85 ; 13.TX@3374.02,2696.85 14.TX@3619.69,2696.85 ; 14.TX@3974.02,2696.85 15.TX@4219.69,2696.85 ; 15.TX@4574.02,2696.85 16.TX@4819.69,2696.85
BANKB_TX2: 21.TX 22.TX 23.TX 24.TX CE15.1 RE15.1 | length 2335.7
  Top Layer w6: v1(2860,670) 2818.87,711.13 2818.87,940 2860,981.13 v1(2860,1080)
  Bottom Layer w6: RE15.1@2860,623.62 v1(2860,670) CE15.1@2860,716.38 ; v1(2860,1080) 2860,1971.85 2885,1996.85 21.TX@3019.68,1996.85 ; 21.TX@3374.02,1996.85 22.TX@3619.69,1996.85 ; 22.TX@3974.02,1996.85 23.TX@4219.69,1996.85 ; 23.TX@4574.02,1996.85 24.TX@4819.69,1996.85
BANKB_TX3: 29.TX 30.TX 31.TX 32.TX CE16.1 RE16.1 | length 3993.5
  Top Layer w6: v1(3100,870) 3081.66,851.66 3081.66,561.07 3106.67,536.05 v1(3106.67,493.33)
  Bottom Layer w6: RE16.1@3072.82,459.48 v1(3106.67,493.33) 3107.76,493.33 CE16.1@3140.51,526.08 ; v1(3100,870) 3115,885 5300,885 5325,910 5325,1275 5303.15,1296.85 32.TX@5174.02,1296.85 ; 29.TX@3374.02,1296.85 30.TX@3619.69,1296.85 ; 30.TX@3974.02,1296.85 31.TX@4219.69,1296.85 ; 31.TX@4574.02,1296.85 32.TX@4819.69,1296.85
CAP0.0: RE1.2 U1.12 | length 290.4
  Bottom Layer w6: RE1.2@2382.25,348.84 2468.84,348.84 2510.16,390.16 U1.12@2655.51,390.16
CAP0.1: RE13.2 U1.13 | length 243.5
  Bottom Layer w6: RE13.2@2421.14,387.73 2482.73,387.73 2504.84,409.84 U1.13@2655.51,409.84
CAP0.2: RE9.2 U1.14 | length 196.7
  Bottom Layer w6: RE9.2@2460.03,426.62 2501.62,426.62 2504.53,429.53 U1.14@2655.51,429.53
CAP0.3: RE5.2 U1.15 | length 163.3
  Bottom Layer w6: RE5.2@2498.92,465.51 2515.22,449.21 U1.15@2655.51,449.21
CAP1.0: RE2.2 U1.16 | length 132.4
  Bottom Layer w6: RE2.2@2537.81,504.41 2573.32,468.9 U1.16@2655.51,468.9
CAP1.1: RE14.2 U1.17 | length 124.6
  Bottom Layer w6: RE14.2@2576.7,543.3 2625.51,494.49 U1.17@2681.1,494.49
CAP1.2: RE10.2 U1.18 | length 124.2
  Bottom Layer w6: RE10.2@2640,576.38 2640,550.79 2650.79,540 2680,540 2700.79,519.21 U1.18@2700.79,494.49
CAP1.3: RE6.2 U1.19 | length 92.4
  Bottom Layer w6: RE6.2@2695,576.38 2695,545 2720.47,519.53 U1.19@2720.47,494.49
CAP2.0: RE3.2 U1.21 | length 105.3
  Bottom Layer w6: U1.21@2759.84,494.49 2759.84,514.84 2785,540 2793,540 2805,552 RE3.2@2805,576.38
CAP2.1: RE15.2 U1.22 | length 135.9
  Bottom Layer w6: U1.22@2779.53,494.49 2779.53,506.91 2812.62,540 2848,540 2860,552 RE15.2@2860,576.38
CAP2.2: RE11.2 U1.23 | length 150.8
  Bottom Layer w6: U1.23@2799.21,494.49 2799.21,506.97 2818.37,526.13 2906.13,526.13 RE11.2@2922.74,542.74
CAP2.3: RE7.2 U1.24 | length 133.4
  Bottom Layer w6: U1.24@2818.9,494.49 RE7.2@2952.27,494.49
CAP3.0: RE4.2 U1.25 | length 152.1
  Bottom Layer w6: U1.25@2844.49,468.9 RE4.2@2996.59,468.9
CAP3.1: RE16.2 U1.26 | length 204.5
  Bottom Layer w6: U1.26@2844.49,449.21 2960.79,449.21 2983.93,426.07 RE16.2@3039.41,426.07
CAP3.2: RE12.2 U1.27 | length 251.4
  Bottom Layer w6: U1.27@2844.49,429.53 2960.47,429.53 3002.82,387.18 RE12.2@3078.3,387.18
CAP3.3: RE8.2 U1.28 | length 298.1
  Bottom Layer w6: U1.28@2844.65,410 2960.38,410 3022.09,348.29 RE8.2@3117.2,348.29
CAPTIVATE_VREG: C3.1 U1.20 | length 86
  Bottom Layer w9: U1.20@2740.16,494.49 2740.16,520.16 2750,530 C3.1@2750,576.38
DETECT: RD33.1 U1.8 | length 1218.8
  Bottom Layer w9: RD33.1@2034.02,601.5 2104.46,531.05 2104.46,155 2124.46,135 2660,135 2681.1,156.1 U1.8@2681.1,305.51
FAULT: RD36.1 U1.5 | length 941.1
  Bottom Layer w9: RD36.1@2034.02,146.5 2048.5,146.5 2053.84,141.16 2053.84,122.11 2100,75.94 2680.49,75.94 2740.16,135.62 U1.5@2740.16,305.51
LED1: D1.1 RD1.2 | length 94.3
  Bottom Layer w10: D1.1@723.62,3720.75 RD1.2@723.62,3815
LED2: D2.1 RD2.2 | length 94.3
  Bottom Layer w10: D2.1@1323.62,3720.75 RD2.2@1323.62,3815
LED3: D3.1 RD3.2 | length 94.3
  Bottom Layer w10: D3.1@1923.62,3720.75 RD3.2@1923.62,3815
LED4: D4.1 RD4.2 | length 98.7
  Bottom Layer w9: D4.1@2523.62,3716.26 RD4.2@2523.62,3815
LED5: D5.1 RD5.2 | length 98.7
  Bottom Layer w9: D5.1@3423.62,3716.26 RD5.2@3423.62,3815
LED6: D6.1 RD6.2 | length 98.7
  Bottom Layer w9: D6.1@4023.62,3716.26 RD6.2@4023.62,3815
LED7: D7.1 RD7.2 | length 98.7
  Bottom Layer w9: D7.1@4623.62,3716.26 RD7.2@4623.62,3815
LED8: D8.1 RD8.2 | length 98.7
  Bottom Layer w9: D8.1@5223.62,3716.26 RD8.2@5223.62,3815
LED9: D9.1 RD9.2 | length 98.7
  Bottom Layer w10: D9.1@723.62,3016.26 RD9.2@723.62,3115
LED10: D10.1 RD10.2 | length 98.7
  Bottom Layer w10: D10.1@1323.62,3016.26 RD10.2@1323.62,3115
LED11: D11.1 RD11.2 | length 98.7
  Bottom Layer w10: D11.1@1923.62,3016.26 RD11.2@1923.62,3115
LED12: D12.1 RD12.2 | length 98.7
  Bottom Layer w10: D12.1@2523.62,3016.26 RD12.2@2523.62,3115
LED13: D13.1 RD13.2 | length 98.7
  Bottom Layer w10: D13.1@3423.62,3016.26 RD13.2@3423.62,3115
LED14: D14.1 RD14.2 | length 98.7
  Bottom Layer w10: D14.1@4023.62,3016.26 RD14.2@4023.62,3115
LED15: D15.1 RD15.2 | length 98.7
  Bottom Layer w10: D15.1@4623.62,3016.26 RD15.2@4623.62,3115
LED16: D16.1 RD16.2 | length 98.7
  Bottom Layer w10: D16.1@5223.62,3016.26 RD16.2@5223.62,3115
LED17: D17.1 RD17.2 | length 98.7
  Bottom Layer w10: D17.1@723.62,2316.26 RD17.2@723.62,2415
LED18: D18.1 RD18.2 | length 98.7
  Bottom Layer w10: D18.1@1323.62,2316.26 RD18.2@1323.62,2415
LED19: D19.1 RD19.2 | length 98.7
  Bottom Layer w10: D19.1@1923.62,2316.26 RD19.2@1923.62,2415
LED20: D20.1 RD20.2 | length 98.7
  Bottom Layer w10: D20.1@2523.62,2316.26 RD20.2@2523.62,2415
LED21: D21.1 RD21.2 | length 98.7
  Bottom Layer w10: D21.1@3423.62,2316.26 RD21.2@3423.62,2415
LED22: D22.1 RD22.2 | length 98.7
  Bottom Layer w10: D22.1@4023.62,2316.26 RD22.2@4023.62,2415
LED23: D23.1 RD23.2 | length 98.7
  Bottom Layer w10: D23.1@4623.62,2316.26 RD23.2@4623.62,2415
LED24: D24.1 RD24.2 | length 98.7
  Bottom Layer w10: D24.1@5223.62,2316.26 RD24.2@5223.62,2415
LED25: D25.1 RD25.2 | length 98.7
  Bottom Layer w10: D25.1@723.62,1616.26 RD25.2@723.62,1715
LED26: D26.1 RD26.2 | length 98.7
  Bottom Layer w10: D26.1@1323.62,1616.26 RD26.2@1323.62,1715
LED27: D27.1 RD27.2 | length 98.7
  Bottom Layer w10: D27.1@1923.62,1616.26 RD27.2@1923.62,1715
LED28: D28.1 RD28.2 | length 98.7
  Bottom Layer w10: D28.1@2523.62,1616.26 RD28.2@2523.62,1715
